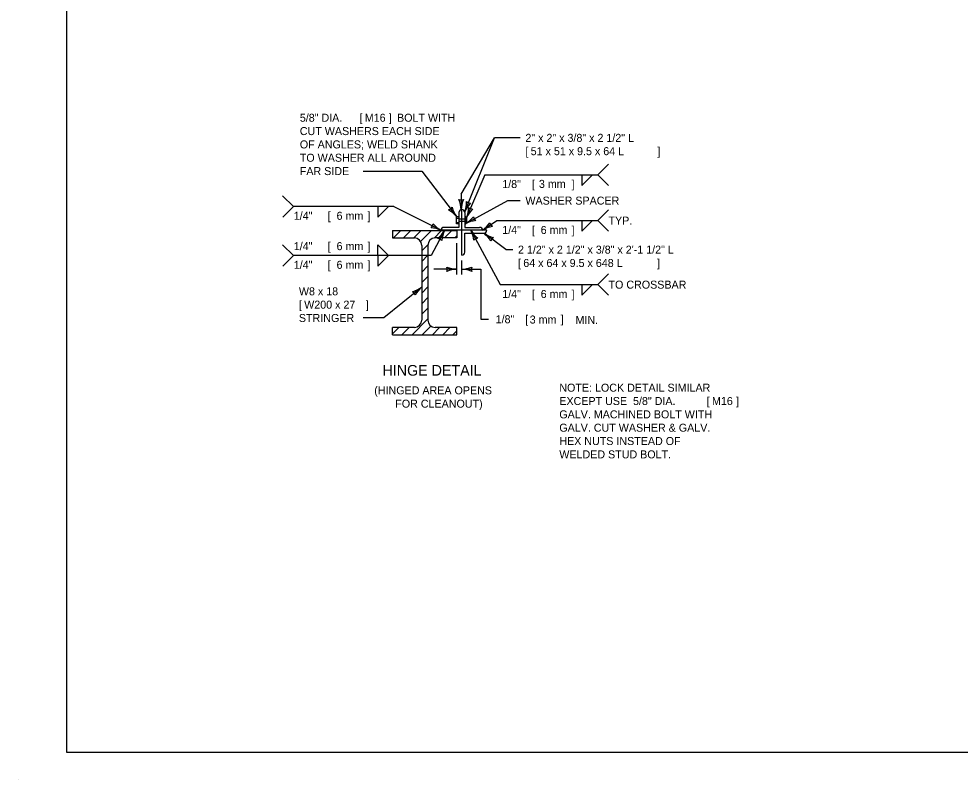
# Model space of a CAD drawing. Extents: x 49991.4 to 50021, y 49987.6 to 50011.4.
# Drawn here: x 49999.02 to 50006.08, y 49987.6 to 49993.3 of the extents above; entities that cross this region are included whole.
import ezdxf

# ---------------------------------------------------------------- set-up
doc = ezdxf.new("R2010")
doc.units = 0
for name, color, linetype in [('Level 1', 7, 'Continuous'), ('Level 2', 7, 'Continuous'), ('Level 3', 7, 'Continuous')]:
    doc.layers.add(name, color=color, linetype=linetype)

msp = doc.modelspace()

# ---------------------------------------------------------------- linework, layer by layer
at = {"layer": 'Level 1'}
for p, q in [((50002.3247, 49991.8464), (50002.3247, 49991.7357)), ((50002.3469, 49991.5271), (50002.3469, 49991.869)), ((50002.3693, 49991.8464), (50002.3693, 49991.7357)), ((50002.3063, 49991.7981), (50002.3063, 49991.816)), ((50002.3063, 49991.816), (50002.3239, 49991.816)), ((50002.3063, 49991.8048), (50002.3239, 49991.8048)), ((50002.3063, 49991.7624), (50002.3063, 49991.7981)), ((50002.3063, 49991.7733), (50002.3239, 49991.7733)), ((50002.3239, 49991.7624), (50002.3063, 49991.7624)), ((50002.3239, 49991.816), (50002.3239, 49991.7981)), ((50002.3239, 49991.8003), (50002.3827, 49991.8003)), ((50002.3239, 49991.7981), (50002.3239, 49991.7624)), ((50002.3239, 49991.7818), (50002.3827, 49991.7818)), ((50002.3693, 49991.8177), (50002.3759, 49991.8177)), ((50002.3693, 49991.7618), (50002.3759, 49991.7618)), ((50002.3759, 49991.8177), (50002.3759, 49991.7618)), ((50002.3759, 49991.8086), (50002.3827, 49991.8086)), ((50002.3759, 49991.7696), (50002.3827, 49991.7696)), ((50002.3827, 49991.8086), (50002.3827, 49991.7696)), ((50001.8277, 49991.7124), (50002.3099, 49991.7124)), ((50001.8277, 49991.7124), (50001.8277, 49991.656)), ((50001.8277, 49991.7124), (50001.8277, 49991.6838)), ((50001.8337, 49991.656), (50001.8883, 49991.7124)), ((50001.9103, 49991.656), (50001.9651, 49991.7124)), ((50001.9871, 49991.656), (50002.0417, 49991.7124)), ((50002.038, 49991.6296), (50002.1183, 49991.7124)), ((50002.1399, 49991.6556), (50002.1949, 49991.7124)), ((50002.5341, 49991.7134), (50002.1915, 49991.7134)), ((50002.3247, 49991.7357), (50002.2141, 49991.7357)), ((50002.2171, 49991.656), (50002.2717, 49991.7124)), ((50002.3099, 49991.7124), (50002.3099, 49991.656)), ((50002.3693, 49991.7357), (50002.4801, 49991.7357)), ((50002.3693, 49991.5493), (50002.3693, 49991.6912)), ((50002.3693, 49991.6912), (50002.5116, 49991.6912)), ((50001.8277, 49991.656), (50001.991, 49991.656)), ((50002.3099, 49991.656), (50002.1466, 49991.656)), ((50002.2937, 49991.656), (50002.3099, 49991.6727)), ((50002.0461, 49991.5588), (50002.0917, 49991.6059)), ((50002.0461, 49991.6009), (50002.0461, 49991.0406)), ((50002.0915, 49991.6009), (50002.0915, 49991.0405)), ((50002.0461, 49991.4798), (50002.0915, 49991.5265)), ((50002.0461, 49991.4006), (50002.0915, 49991.4473)), ((50002.0461, 49991.3215), (50002.0915, 49991.3683)), ((50002.0461, 49991.2425), (50002.0915, 49991.2893)), ((50002.0461, 49991.1633), (50002.0915, 49991.2101)), ((50002.0461, 49991.0842), (50002.0915, 49991.131)), ((50001.9733, 49990.9298), (50002.0915, 49991.0502)), ((50001.8277, 49990.9298), (50001.8277, 49990.986)), ((50001.9911, 49990.9856), (50001.8277, 49990.986)), ((50001.8277, 49990.938), (50001.8742, 49990.9859)), ((50001.8967, 49990.9298), (50001.9507, 49990.9857)), ((50002.0501, 49990.9298), (50002.1142, 49990.996)), ((50002.1267, 49990.9298), (50002.1805, 49990.9856)), ((50002.3099, 49990.9859), (50002.1466, 49990.9855)), ((50002.2033, 49990.9298), (50002.2575, 49990.9858)), ((50002.3099, 49990.9298), (50002.3099, 49990.9859)), ((50001.8277, 49990.9298), (50001.8277, 49990.9584)), ((50001.8277, 49990.9298), (50002.3099, 49990.9298)), ((50002.2799, 49990.9298), (50002.3099, 49990.9608)), ((49999.0245, 49987.5988), (49999.0245, 49987.5988))]:
    msp.add_line(p, q, dxfattribs=at)
msp.add_lwpolyline([(49999.3835, 49998.9992), (50016.7501, 49998.9992), (50016.7501, 49987.7988), (49999.3835, 49987.7988)], close=True, dxfattribs=at)
for centre, radius, start, end in [((50002.347, 49991.8467), 0.0223, 90.23486, 180.78825), ((50002.3471, 49991.8469), 0.0222, 358.84999, 90.64072), ((50002.2121, 49991.7151), 0.0207, 84.5429, 184.69147), ((50002.481, 49991.7143), 0.0215, 357.79015, 92.4662), ((50002.5124, 49991.7129), 0.0217, 267.95357, 1.34516), ((50001.991, 49991.6009), 0.0551, 0, 90), ((50002.1466, 49991.6009), 0.0551, 90, 180), ((50002.348, 49991.5484), 0.0213, 266.86828, 2.61786), ((50001.9911, 49991.0406), 0.0551, 270, 0), ((50002.1466, 49991.0405), 0.0551, 180, 270)]:
    msp.add_arc(centre, radius, start, end, dxfattribs=at)
at = {"layer": 'Level 3'}
for p, q in [((50002.3417, 49991.9853), (50002.5921, 49992.4068)), ((50002.3687, 49991.8521), (50002.5921, 49992.4068)), ((50002.7835, 49992.4068), (50002.5921, 49992.4068)), ((50003.3668, 49992.1304), (50003.4468, 49992.2104)), ((50001.6067, 49992.1575), (50002.0475, 49992.1575)), ((50002.0475, 49992.1575), (50002.3063, 49991.816)), ((50002.5203, 49992.1304), (50002.3827, 49991.8086)), ((50002.5203, 49992.1304), (50003.3668, 49992.1304)), ((50003.2468, 49992.1304), (50003.2468, 49992.0504)), ((50003.2468, 49992.0504), (50003.3268, 49992.1304)), ((50003.3668, 49992.1304), (50003.4468, 49992.0504)), ((50001.0026, 49991.9726), (50001.0833, 49991.8926)), ((50002.3417, 49991.9853), (50002.3417, 49991.8684)), ((50002.3759, 49991.7643), (50002.6906, 49991.9362)), ((50002.6906, 49991.9362), (50002.7835, 49991.9362)), ((50001.0036, 49991.8129), (50001.0833, 49991.8926)), ((50001.8361, 49991.8926), (50001.0833, 49991.8926)), ((50001.7161, 49991.8126), (50001.7961, 49991.8926)), ((50001.7161, 49991.8926), (50001.7161, 49991.8126)), ((50001.7161, 49991.8126), (50001.7961, 49991.8926)), ((50001.8361, 49991.8926), (50002.1915, 49991.7134)), ((50003.3668, 49991.7863), (50003.4468, 49991.8663)), ((50002.5025, 49991.7134), (50002.6081, 49991.7863)), ((50002.6081, 49991.7863), (50003.3668, 49991.7863)), ((50003.2468, 49991.7863), (50003.2468, 49991.7063)), ((50003.2468, 49991.7063), (50003.3268, 49991.7863)), ((50003.3668, 49991.7863), (50003.4468, 49991.7063)), ((50002.2165, 49991.7124), (50002.1179, 49991.5248)), ((50002.415, 49991.7134), (50002.6338, 49991.3062)), ((50002.6762, 49991.5687), (50002.5132, 49991.6912)), ((50002.3101, 49991.3814), (50002.3101, 49991.616)), ((50001.0026, 49991.6048), (50001.0833, 49991.5248)), ((50001.7161, 49991.6048), (50001.7961, 49991.5248)), ((50001.7161, 49991.5248), (50001.7161, 49991.6048)), ((50002.6762, 49991.5687), (50002.728, 49991.5687)), ((50001.0036, 49991.4451), (50001.0833, 49991.5248)), ((50002.1179, 49991.5248), (50001.0833, 49991.5248)), ((50001.7161, 49991.5248), (50001.7161, 49991.4448)), ((50001.7161, 49991.4448), (50001.7961, 49991.5248)), ((50002.3463, 49991.3816), (50002.3463, 49991.4871)), ((50002.3101, 49991.4214), (50002.1367, 49991.4214)), ((50002.3463, 49991.4216), (50002.4889, 49991.4216)), ((50002.4889, 49991.4216), (50002.4889, 49991.1146)), ((50003.3668, 49991.3062), (50003.4468, 49991.3862)), ((50002.0461, 49991.2883), (50001.7623, 49991.0562)), ((50002.6338, 49991.3062), (50003.3668, 49991.3062)), ((50003.2468, 49991.3062), (50003.2468, 49991.2262)), ((50003.2468, 49991.2262), (50003.3268, 49991.3062)), ((50003.3668, 49991.3062), (50003.4468, 49991.2262)), ((50001.7623, 49991.0562), (50001.6072, 49991.0562))]:
    msp.add_line(p, q, dxfattribs=at)
msp.add_lwpolyline([(50002.4889, 49991.1146), (50002.4889, 49991.047), (50002.5463, 49991.047)], dxfattribs=at)
for centre, radius, start, end in [((50002.3417, 49991.9966), 0.0548, 252.13882, 287.86118), ((50002.109, 49991.8569), 0.233, 2.82731, 22.07716), ((50002.5638, 49991.8592), 0.2223, 157.45601, 177.63952), ((50002.1485, 49991.9282), 0.233, 340.89545, 0.1453), ((50002.5713, 49991.7605), 0.2223, 135.52415, 155.70766), ((50002.4166, 49991.9709), 0.0548, 230.20696, 265.92932), ((50002.2288, 49991.9182), 0.0548, 289.29487, 325.01723), ((50002.1278, 49991.6663), 0.233, 39.98336, 59.23321), ((50002.4889, 49991.9429), 0.2223, 194.61206, 214.79557), ((50002.1642, 49991.8895), 0.233, 339.68042, 358.93027), ((50002.5833, 49991.7129), 0.2223, 134.30912, 154.49263), ((50002.4331, 49991.9265), 0.0548, 228.99193, 264.71429), ((50002.077, 49991.7712), 0.0548, 315.38064, 351.103), ((50002.2997, 49991.9077), 0.2223, 220.69783, 240.88134), ((50002.2543, 49991.9631), 0.233, 301.4653, 320.71515), ((50002.4743, 49991.565), 0.2223, 96.094, 116.27751), ((50002.4884, 49991.8258), 0.0548, 190.77681, 226.49917), ((50002.3611, 49991.8986), 0.233, 307.3659, 326.61575), ((50002.6081, 49991.7861), 0.0548, 196.67741, 232.39977), ((50002.097, 49991.5005), 0.233, 66.06913, 85.31898), ((50002.0241, 49991.8239), 0.2223, 309.73021, 329.91372), ((50002.4278, 49991.6143), 0.233, 155.10151, 174.35136), ((50002.215, 49991.6164), 0.2223, 5.70295, 25.88646), ((50002.6145, 49991.8337), 0.233, 211.07425, 230.3241), ((50002.6209, 49991.5253), 0.2223, 101.9946, 122.17811), ((50002.3723, 49991.5193), 0.2223, 30.52131, 50.70482), ((50002.6437, 49991.8842), 0.233, 235.89261, 255.14246), ((50002.1568, 49991.5989), 0.0548, 44.41302, 80.13538), ((50002.4757, 49991.6005), 0.0548, 100.38576, 136.10812), ((50002.6156, 49991.6143), 0.0548, 125.20412, 160.92648), ((50002.3193, 49991.6435), 0.2223, 247.45601, 267.63952), ((50002.1819, 49991.4214), 0.0548, 342.13882, 17.86118), ((50002.3216, 49991.1887), 0.233, 92.82731, 112.07716), ((50002.3348, 49991.6544), 0.233, 272.82731, 292.07716), ((50002.3371, 49991.1995), 0.2223, 67.45601, 87.63952), ((50002.4745, 49991.4216), 0.0548, 162.13882, 197.86118), ((50001.9126, 49991.466), 0.2223, 286.73158, 306.91509), ((50002.2023, 49991.1154), 0.233, 132.10288, 151.35273), ((50001.9469, 49991.2071), 0.0548, 21.41439, 57.13675)]:
    msp.add_arc(centre, radius, start, end, dxfattribs=at)

# ---------------------------------------------------------------- texts
at = {"layer": 'Level 2'}
for s, height, p in [('5/8" DIA. ', 0.06, (50001.1318, 49992.5275)), ('[', 0.06, (50001.5793, 49992.5275)), ('M16', 0.06, (50001.619, 49992.5275)), (']', 0.06, (50001.799, 49992.5275)), (' BOLT WITH', 0.06, (50001.8387, 49992.5275)), ('CUT WASHERS EACH SIDE', 0.06, (50001.1318, 49992.4275)), ('2" x 2" x 3/8" x 2 1/2" L', 0.06, (50002.8235, 49992.3768)), ('OF ANGLES; WELD SHANK', 0.06, (50001.1318, 49992.3275)), ('[', 0.06, (50002.8235, 49992.2768)), ('51 x 51 x 9.5 x 64 L', 0.06, (50002.8632, 49992.2768)), (']', 0.06, (50003.8126, 49992.2768)), ('TO WASHER ALL AROUND', 0.06, (50001.1318, 49992.2275)), ('FAR SIDE', 0.06, (50001.1318, 49992.1275)), ('1/8" ', 0.06, (50002.6498, 49992.0304)), ('[', 0.06, (50002.8719, 49992.0304)), ('3 mm', 0.06, (50002.9248, 49992.0316)), (']', 0.06, (50003.1695, 49992.0304)), ('WASHER SPACER', 0.06, (50002.8235, 49991.9062)), ('1/4" ', 0.06, (50001.0864, 49991.7926)), ('[', 0.06, (50001.3411, 49991.7926)), ('6 mm', 0.06, (50001.4074, 49991.7926)), (']', 0.06, (50001.6388, 49991.7926)), ('TYP.', 0.06, (50003.4468, 49991.7563)), ('1/4" ', 0.06, (50002.6498, 49991.6863)), ('[', 0.06, (50002.8719, 49991.6863)), ('6 mm', 0.06, (50002.9382, 49991.6863)), (']', 0.06, (50003.1695, 49991.6863)), ('1/4" ', 0.06, (50001.0864, 49991.5648)), ('[', 0.06, (50001.3411, 49991.5648)), ('6 mm', 0.06, (50001.4074, 49991.5648)), (']', 0.06, (50001.6388, 49991.5648)), ('2 1/2" x 2 1/2" x 3/8" x 2\'-1 1/2" L', 0.06, (50002.768, 49991.5387)), ('1/4" ', 0.06, (50001.0864, 49991.4248)), ('[', 0.06, (50001.3411, 49991.4248)), ('6 mm', 0.06, (50001.4074, 49991.4248)), (']', 0.06, (50001.6388, 49991.4248)), ('[', 0.06, (50002.768, 49991.4387)), ('64 x 64 x 9.5 x 648 L', 0.06, (50002.8076, 49991.4387)), (']', 0.06, (50003.8109, 49991.4387)), ('TO CROSSBAR', 0.06, (50003.4468, 49991.2762)), ('W8 x 18', 0.06, (50001.1248, 49991.2262)), ('1/4" ', 0.06, (50002.6498, 49991.2062)), ('[', 0.06, (50002.8719, 49991.2062)), ('6 mm', 0.06, (50002.9382, 49991.2062)), (']', 0.06, (50003.1695, 49991.2062)), ('[', 0.06, (50001.1248, 49991.1262)), (']', 0.06, (50001.6266, 49991.1262)), ('W200 x 27', 0.06, (50001.1645, 49991.1262)), ('STRINGER', 0.06, (50001.1248, 49991.0262)), ('1/8" ', 0.06, (50002.6002, 49991.017)), ('[', 0.06, (50002.8223, 49991.017)), ('3 mm', 0.06, (50002.8558, 49991.0146)), ('] ', 0.06, (50003.0884, 49991.0182)), ('MIN.', 0.06, (50003.1993, 49991.0121)), ('HINGE DETAIL', 0.08, (50001.7519, 49990.6239)), ('NOTE: LOCK DETAIL SIMILAR', 0.06, (50003.0778, 49990.5037)), ('(HINGED AREA OPENS', 0.06, (50001.69, 49990.4839)), ('FOR CLEANOUT)', 0.06, (50001.8476, 49990.3839)), ('EXCEPT USE  5/8" DIA. ', 0.06, (50003.0778, 49990.4037)), ('[', 0.06, (50004.183, 49990.4037)), ('M16', 0.06, (50004.2227, 49990.4037)), (']', 0.06, (50004.4027, 49990.4037)), ('GALV. MACHINED BOLT WITH', 0.06, (50003.0778, 49990.3037)), ('GALV. CUT WASHER & GALV.', 0.06, (50003.0778, 49990.2037)), ('HEX NUTS INSTEAD OF', 0.06, (50003.0778, 49990.1037)), ('WELDED STUD BOLT.', 0.06, (50003.0778, 49990.0037))]:
    msp.add_text(s, height=height, dxfattribs=at).set_placement(p)

doc.saveas('drawing.dxf')
